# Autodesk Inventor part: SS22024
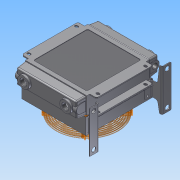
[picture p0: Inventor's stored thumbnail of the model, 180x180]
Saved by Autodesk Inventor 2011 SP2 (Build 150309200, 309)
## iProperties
Created: 2015-12
Part Number: SS22024
Material: Сталь
Document SubType Name: Modeling
Designer: Дорохин
Mass: 7000 g
Surface Area: 5612.32 cm^2
Volume: 4411.6 cm^3
Density: 1.58673 g/cm^3
Author: Дорохин
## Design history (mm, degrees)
derived "374_SS2200300A-PE.iam"
sketch "Эскиз2"
  geometry: L1 (230, 0)-(0, 0) reference; L2 (-25, -216.5)-(-25, -16.5) reference; L3 (0, -233)-(230, -233) reference; L4 (255, -16.5)-(255, -216.5) reference; L5 (20, -218)-(210, -218); L6 (215, -213)-(215, -20); L7 (210, -15)-(20, -15); L8 (15, -20)-(15, -213); A1 r 5 centre (20, -213) between (15, -213) and (20, -218); A2 r 5 centre (20, -20) between (20, -15) and (15, -20); A3 r 5 centre (210, -20) between (215, -20) and (210, -15); A4 r 5 centre (210, -213) between (210, -218) and (215, -213); 1 further point
  constraints: 8 end point, 8 point on circle, 8 tangent, 4 centre point, 3 equal radius, 2 parallel, 1 horizontal, 1 perpendicular
  dimensions: "d1" = 40 distance between parallel lines of L4 L6; "d2" = 40 distance between parallel lines of L2 L8 (= d1); "d3" = 15 distance between parallel lines of L3 L5; "d4" = 15 distance between parallel lines of L1 L7 (= d3); "d5" = 5 radius of A1
extrude "Выдавливание1" cut sketch "Эскиз2" distance "d6" = 2; taper "d7" = 0 deg
feature "Резьба1" dims "d8" = 10, "d9" = 0
feature "Резьба2" dims "d10" = 10, "d11" = 0
feature "Резьба3" dims "d12" = 10, "d13" = 0
sketch "Эскиз3"
  geometry: L1 (-5, -5)-(75, -5); L2 (75, -5)-(75, 115); L3 (75, 115)-(-5, 115); L4 (-5, 115)-(-5, -5); L5 (0, 110)-(70, 110) reference; L6 (70, 110)-(70, 0) reference; L7 (70, 0)-(0, 0) reference; L8 (0, 0)-(0, 110) reference; L9 (70, 115)-(0, 115) reference; 4 further points
  constraints: 8 end point, 4 point on line, 2 parallel, 1 horizontal, 1 perpendicular
extrude "Выдавливание2" cut sketch "Эскиз3" distance "d14" = 50; taper "d15" = 0 deg
node "Твердое тело1"
node "None.ipt:1"
node "None_1.ipt:1"
feature "Производный составной элемент1"
node "Проецирование ребер1"
